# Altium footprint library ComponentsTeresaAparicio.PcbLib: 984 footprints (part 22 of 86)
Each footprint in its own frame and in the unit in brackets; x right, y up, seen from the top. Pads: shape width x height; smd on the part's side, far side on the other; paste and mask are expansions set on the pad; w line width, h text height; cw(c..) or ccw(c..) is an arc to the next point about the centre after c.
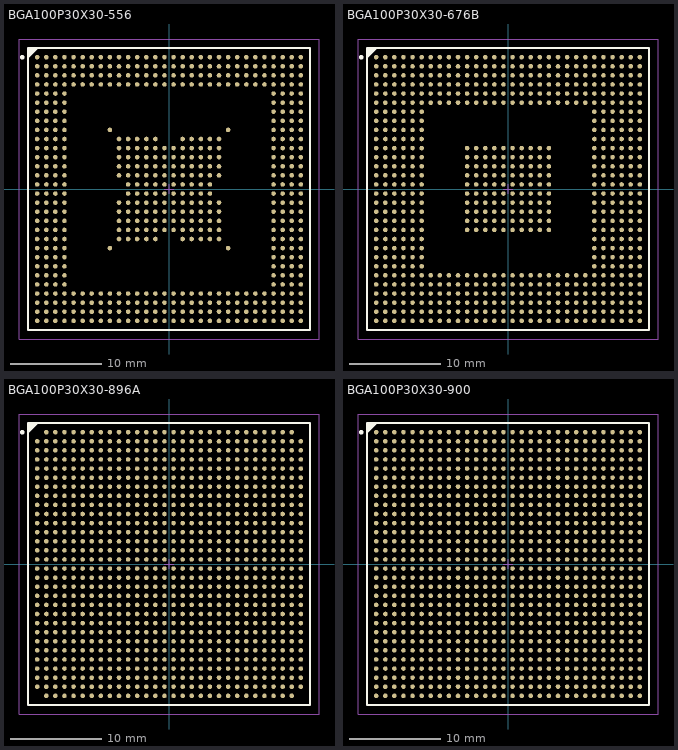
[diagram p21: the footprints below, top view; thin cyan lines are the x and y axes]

## BGA100P30X30-556 [mm] "556-Ball Fine Pitch Ball Grid Array 1.00 mm Pitch (FG556)"
height 2.6
pads (556):
  round 0.5 smd: A1(-14.5,14.5) A2(-13.5,14.5) A3(-12.5,14.5) A4(-11.5,14.5) A5(-10.5,14.5) A6(-9.5,14.5) A7(-8.5,14.5) A8(-7.5,14.5) A9(-6.5,14.5) A10(-5.5,14.5) A11(-4.5,14.5) A12(-3.5,14.5) A13(-2.5,14.5) A14(-1.5,14.5) A15(-0.5,14.5) A16(0.5,14.5) A17(1.5,14.5) A18(2.5,14.5) A19(3.5,14.5) A20(4.5,14.5) A21(5.5,14.5) A22(6.5,14.5) A23(7.5,14.5) A24(8.5,14.5) A25(9.5,14.5) A26(10.5,14.5) A27(11.5,14.5) A28(12.5,14.5) A29(13.5,14.5) A30(14.5,14.5) AA1(-14.5,-5.5) AA2(-13.5,-5.5) AA3(-12.5,-5.5) AA4(-11.5,-5.5) AA10(-5.5,-5.5) AA11(-4.5,-5.5) AA12(-3.5,-5.5) AA13(-2.5,-5.5) AA14(-1.5,-5.5) AA17(1.5,-5.5) AA18(2.5,-5.5) AA19(3.5,-5.5) AA20(4.5,-5.5) AA21(5.5,-5.5) AA27(11.5,-5.5) AA28(12.5,-5.5) AA29(13.5,-5.5) AA30(14.5,-5.5) AB1(-14.5,-6.5) AB2(-13.5,-6.5) AB3(-12.5,-6.5) AB4(-11.5,-6.5) AB9(-6.5,-6.5) AB22(6.5,-6.5) AB27(11.5,-6.5) AB28(12.5,-6.5) AB29(13.5,-6.5) AB30(14.5,-6.5) AC1(-14.5,-7.5) AC2(-13.5,-7.5) AC3(-12.5,-7.5) AC4(-11.5,-7.5) AC27(11.5,-7.5) AC28(12.5,-7.5) AC29(13.5,-7.5) AC30(14.5,-7.5) AD1(-14.5,-8.5) AD2(-13.5,-8.5) AD3(-12.5,-8.5) AD4(-11.5,-8.5) AD27(11.5,-8.5) AD28(12.5,-8.5) AD29(13.5,-8.5) AD30(14.5,-8.5) AE1(-14.5,-9.5) AE2(-13.5,-9.5) AE3(-12.5,-9.5) AE4(-11.5,-9.5) AE27(11.5,-9.5) AE28(12.5,-9.5) AE29(13.5,-9.5) AE30(14.5,-9.5) AF1(-14.5,-10.5) AF2(-13.5,-10.5) AF3(-12.5,-10.5) AF4(-11.5,-10.5) AF27(11.5,-10.5) AF28(12.5,-10.5) AF29(13.5,-10.5) AF30(14.5,-10.5) AG1(-14.5,-11.5) AG2(-13.5,-11.5) AG3(-12.5,-11.5) AG4(-11.5,-11.5) AG5(-10.5,-11.5) AG6(-9.5,-11.5) AG7(-8.5,-11.5) AG8(-7.5,-11.5) AG9(-6.5,-11.5) AG10(-5.5,-11.5) AG11(-4.5,-11.5) AG12(-3.5,-11.5) AG13(-2.5,-11.5) AG14(-1.5,-11.5) AG15(-0.5,-11.5) AG16(0.5,-11.5) AG17(1.5,-11.5) AG18(2.5,-11.5) AG19(3.5,-11.5) AG20(4.5,-11.5) AG21(5.5,-11.5) AG22(6.5,-11.5) AG23(7.5,-11.5) AG24(8.5,-11.5) AG25(9.5,-11.5) AG26(10.5,-11.5) AG27(11.5,-11.5) AG28(12.5,-11.5) AG29(13.5,-11.5) AG30(14.5,-11.5) AH1(-14.5,-12.5) AH2(-13.5,-12.5) AH3(-12.5,-12.5) AH4(-11.5,-12.5) AH5(-10.5,-12.5) AH6(-9.5,-12.5) AH7(-8.5,-12.5) AH8(-7.5,-12.5) AH9(-6.5,-12.5) AH10(-5.5,-12.5) AH11(-4.5,-12.5) AH12(-3.5,-12.5) AH13(-2.5,-12.5) AH14(-1.5,-12.5) AH15(-0.5,-12.5) AH16(0.5,-12.5) AH17(1.5,-12.5) AH18(2.5,-12.5) AH19(3.5,-12.5) AH20(4.5,-12.5) AH21(5.5,-12.5) AH22(6.5,-12.5) AH23(7.5,-12.5) AH24(8.5,-12.5) AH25(9.5,-12.5) AH26(10.5,-12.5) AH27(11.5,-12.5) AH28(12.5,-12.5) AH29(13.5,-12.5) AH30(14.5,-12.5) AJ1(-14.5,-13.5) AJ2(-13.5,-13.5) AJ3(-12.5,-13.5) AJ4(-11.5,-13.5) AJ5(-10.5,-13.5) AJ6(-9.5,-13.5) AJ7(-8.5,-13.5) AJ8(-7.5,-13.5) AJ9(-6.5,-13.5) AJ10(-5.5,-13.5) AJ11(-4.5,-13.5) AJ12(-3.5,-13.5) AJ13(-2.5,-13.5) AJ14(-1.5,-13.5) AJ15(-0.5,-13.5) AJ16(0.5,-13.5) AJ17(1.5,-13.5) AJ18(2.5,-13.5) AJ19(3.5,-13.5) AJ20(4.5,-13.5) AJ21(5.5,-13.5) AJ22(6.5,-13.5) AJ23(7.5,-13.5) AJ24(8.5,-13.5) AJ25(9.5,-13.5) AJ26(10.5,-13.5) AJ27(11.5,-13.5) AJ28(12.5,-13.5) AJ29(13.5,-13.5) AJ30(14.5,-13.5) AK1(-14.5,-14.5) AK2(-13.5,-14.5) AK3(-12.5,-14.5) AK4(-11.5,-14.5) AK5(-10.5,-14.5) AK6(-9.5,-14.5) AK7(-8.5,-14.5) AK8(-7.5,-14.5) AK9(-6.5,-14.5) AK10(-5.5,-14.5) AK11(-4.5,-14.5) AK12(-3.5,-14.5) AK13(-2.5,-14.5) AK14(-1.5,-14.5) AK15(-0.5,-14.5) AK16(0.5,-14.5) AK17(1.5,-14.5) AK18(2.5,-14.5) AK19(3.5,-14.5) AK20(4.5,-14.5) AK21(5.5,-14.5) AK22(6.5,-14.5) AK23(7.5,-14.5) AK24(8.5,-14.5) AK25(9.5,-14.5) AK26(10.5,-14.5) AK27(11.5,-14.5) AK28(12.5,-14.5) AK29(13.5,-14.5) AK30(14.5,-14.5) B1(-14.5,13.5) B2(-13.5,13.5) B3(-12.5,13.5) B4(-11.5,13.5) B5(-10.5,13.5) B6(-9.5,13.5) B7(-8.5,13.5) B8(-7.5,13.5) B9(-6.5,13.5) B10(-5.5,13.5) B11(-4.5,13.5) B12(-3.5,13.5) B13(-2.5,13.5) B14(-1.5,13.5) B15(-0.5,13.5) B16(0.5,13.5) B17(1.5,13.5) B18(2.5,13.5) B19(3.5,13.5) B20(4.5,13.5) B21(5.5,13.5) B22(6.5,13.5) B23(7.5,13.5) B24(8.5,13.5) B25(9.5,13.5) B26(10.5,13.5) B27(11.5,13.5) B28(12.5,13.5) B29(13.5,13.5) B30(14.5,13.5) C1(-14.5,12.5) C2(-13.5,12.5) C3(-12.5,12.5) C4(-11.5,12.5) C5(-10.5,12.5) C6(-9.5,12.5) C7(-8.5,12.5) C8(-7.5,12.5) C9(-6.5,12.5) C10(-5.5,12.5) C11(-4.5,12.5) C12(-3.5,12.5) C13(-2.5,12.5) C14(-1.5,12.5) C15(-0.5,12.5) C16(0.5,12.5) C17(1.5,12.5) C18(2.5,12.5) C19(3.5,12.5) C20(4.5,12.5) C21(5.5,12.5) C22(6.5,12.5) C23(7.5,12.5) C24(8.5,12.5) C25(9.5,12.5) C26(10.5,12.5) C27(11.5,12.5) C28(12.5,12.5) C29(13.5,12.5) C30(14.5,12.5) D1(-14.5,11.5) D2(-13.5,11.5) D3(-12.5,11.5) D4(-11.5,11.5) D5(-10.5,11.5) D6(-9.5,11.5) D7(-8.5,11.5) D8(-7.5,11.5) D9(-6.5,11.5) D10(-5.5,11.5) D11(-4.5,11.5) D12(-3.5,11.5) D13(-2.5,11.5) D14(-1.5,11.5) D15(-0.5,11.5) D16(0.5,11.5) D17(1.5,11.5) D18(2.5,11.5) D19(3.5,11.5) D20(4.5,11.5) D21(5.5,11.5) D22(6.5,11.5) D23(7.5,11.5) D24(8.5,11.5) D25(9.5,11.5) D26(10.5,11.5) D27(11.5,11.5) D28(12.5,11.5) D29(13.5,11.5) D30(14.5,11.5) E1(-14.5,10.5) E2(-13.5,10.5) E3(-12.5,10.5) E4(-11.5,10.5) E27(11.5,10.5) E28(12.5,10.5) E29(13.5,10.5) E30(14.5,10.5) F1(-14.5,9.5) F2(-13.5,9.5) F3(-12.5,9.5) F4(-11.5,9.5) F27(11.5,9.5) F28(12.5,9.5) F29(13.5,9.5) F30(14.5,9.5) G1(-14.5,8.5) G2(-13.5,8.5) G3(-12.5,8.5) G4(-11.5,8.5) G27(11.5,8.5) G28(12.5,8.5) G29(13.5,8.5) G30(14.5,8.5) H1(-14.5,7.5) H2(-13.5,7.5) H3(-12.5,7.5) H4(-11.5,7.5) H27(11.5,7.5) H28(12.5,7.5) H29(13.5,7.5) H30(14.5,7.5) J1(-14.5,6.5) J2(-13.5,6.5) J3(-12.5,6.5) J4(-11.5,6.5) J9(-6.5,6.5) J22(6.5,6.5) J27(11.5,6.5) J28(12.5,6.5) J29(13.5,6.5) J30(14.5,6.5) K1(-14.5,5.5) K2(-13.5,5.5) K3(-12.5,5.5) K4(-11.5,5.5) K10(-5.5,5.5) K11(-4.5,5.5) K12(-3.5,5.5) K13(-2.5,5.5) K14(-1.5,5.5) K17(1.5,5.5) K18(2.5,5.5) K19(3.5,5.5) K20(4.5,5.5) K21(5.5,5.5) K27(11.5,5.5) K28(12.5,5.5) K29(13.5,5.5) K30(14.5,5.5) L1(-14.5,4.5) L2(-13.5,4.5) L3(-12.5,4.5) L4(-11.5,4.5) L10(-5.5,4.5) L11(-4.5,4.5) L12(-3.5,4.5) L13(-2.5,4.5) L14(-1.5,4.5) L15(-0.5,4.5) L16(0.5,4.5) L17(1.5,4.5) L18(2.5,4.5) L19(3.5,4.5) L20(4.5,4.5) L21(5.5,4.5) L27(11.5,4.5) L28(12.5,4.5) L29(13.5,4.5) L30(14.5,4.5) M1(-14.5,3.5) M2(-13.5,3.5) M3(-12.5,3.5) M4(-11.5,3.5) M10(-5.5,3.5) M11(-4.5,3.5) M12(-3.5,3.5) M13(-2.5,3.5) M14(-1.5,3.5) M15(-0.5,3.5) M16(0.5,3.5) M17(1.5,3.5) M18(2.5,3.5) M19(3.5,3.5) M20(4.5,3.5) M21(5.5,3.5) M27(11.5,3.5) M28(12.5,3.5) M29(13.5,3.5) M30(14.5,3.5) N1(-14.5,2.5) N2(-13.5,2.5) N3(-12.5,2.5) N4(-11.5,2.5) N10(-5.5,2.5) N11(-4.5,2.5) N12(-3.5,2.5) N13(-2.5,2.5) N14(-1.5,2.5) N15(-0.5,2.5) N16(0.5,2.5) N17(1.5,2.5) N18(2.5,2.5) N19(3.5,2.5) N20(4.5,2.5) N21(5.5,2.5) N27(11.5,2.5) N28(12.5,2.5) N29(13.5,2.5) N30(14.5,2.5) P1(-14.5,1.5) P2(-13.5,1.5) P3(-12.5,1.5) P4(-11.5,1.5) P10(-5.5,1.5) P11(-4.5,1.5) P12(-3.5,1.5) P13(-2.5,1.5) P14(-1.5,1.5) P15(-0.5,1.5) P16(0.5,1.5) P17(1.5,1.5) P18(2.5,1.5) P19(3.5,1.5) P20(4.5,1.5) P21(5.5,1.5) P27(11.5,1.5) P28(12.5,1.5) P29(13.5,1.5) P30(14.5,1.5) R1(-14.5,0.5) R2(-13.5,0.5) R3(-12.5,0.5) R4(-11.5,0.5) R11(-4.5,0.5) R12(-3.5,0.5) R13(-2.5,0.5) R14(-1.5,0.5) R15(-0.5,0.5) R16(0.5,0.5) R17(1.5,0.5) R18(2.5,0.5) R19(3.5,0.5) R20(4.5,0.5) R27(11.5,0.5) R28(12.5,0.5) R29(13.5,0.5) R30(14.5,0.5) T1(-14.5,-0.5) T2(-13.5,-0.5) T3(-12.5,-0.5) T4(-11.5,-0.5) T11(-4.5,-0.5) T12(-3.5,-0.5) T13(-2.5,-0.5) T14(-1.5,-0.5) T15(-0.5,-0.5) T16(0.5,-0.5) T17(1.5,-0.5) T18(2.5,-0.5) T19(3.5,-0.5) T20(4.5,-0.5) T27(11.5,-0.5) T28(12.5,-0.5) T29(13.5,-0.5) T30(14.5,-0.5) U1(-14.5,-1.5) U2(-13.5,-1.5) U3(-12.5,-1.5) U4(-11.5,-1.5) U10(-5.5,-1.5) U11(-4.5,-1.5) U12(-3.5,-1.5) U13(-2.5,-1.5) U14(-1.5,-1.5) U15(-0.5,-1.5) U16(0.5,-1.5) U17(1.5,-1.5) U18(2.5,-1.5) U19(3.5,-1.5) U20(4.5,-1.5) U21(5.5,-1.5) U27(11.5,-1.5) U28(12.5,-1.5) U29(13.5,-1.5) U30(14.5,-1.5) V1(-14.5,-2.5) V2(-13.5,-2.5) V3(-12.5,-2.5) V4(-11.5,-2.5) V10(-5.5,-2.5) V11(-4.5,-2.5) V12(-3.5,-2.5) V13(-2.5,-2.5) V14(-1.5,-2.5) V15(-0.5,-2.5) V16(0.5,-2.5) V17(1.5,-2.5) V18(2.5,-2.5) V19(3.5,-2.5) V20(4.5,-2.5) V21(5.5,-2.5) V27(11.5,-2.5) V28(12.5,-2.5) V29(13.5,-2.5) V30(14.5,-2.5) W1(-14.5,-3.5) W2(-13.5,-3.5) W3(-12.5,-3.5) W4(-11.5,-3.5) W10(-5.5,-3.5) W11(-4.5,-3.5) W12(-3.5,-3.5) W13(-2.5,-3.5) W14(-1.5,-3.5) W15(-0.5,-3.5) W16(0.5,-3.5) W17(1.5,-3.5) W18(2.5,-3.5) W19(3.5,-3.5) W20(4.5,-3.5) W21(5.5,-3.5) W27(11.5,-3.5) W28(12.5,-3.5) W29(13.5,-3.5) W30(14.5,-3.5) Y1(-14.5,-4.5) Y2(-13.5,-4.5) Y3(-12.5,-4.5) Y4(-11.5,-4.5) Y10(-5.5,-4.5) Y11(-4.5,-4.5) Y12(-3.5,-4.5) Y13(-2.5,-4.5) Y14(-1.5,-4.5) Y15(-0.5,-4.5) Y16(0.5,-4.5) Y17(1.5,-4.5) Y18(2.5,-4.5) Y19(3.5,-4.5) Y20(4.5,-4.5) Y21(5.5,-4.5) Y27(11.5,-4.5) Y28(12.5,-4.5) Y29(13.5,-4.5) Y30(14.5,-4.5)
Top Overlay:
  circle w0.25: c-16.15,14.5 r0.125
  region: -14.5,15.5 -15.5,14.5 -15.5,15.5
  lines w0.2: -15.5,14.5 -14.5,15.5 ; -15.5,-15.5 -15.5,15.5 15.5,15.5 15.5,-15.5 -15.5,-15.5
Mechanical 13:
  lines w0.1: -15.5,-15.5 -15.5,15.5 15.5,15.5 15.5,-15.5 -15.5,-15.5
Mechanical 15:
  lines w0.1: -0.5,0 0.5,0 ; 0,-0.5 0,0.5 ; -16.5,-16.5 -16.5,16.5 16.5,16.5 16.5,-16.5 -16.5,-16.5
3D body: height 0, standoff 0, extent -15.5,-15.5 15.5,15.5

## BGA100P30X30-676B [mm] "BGA, 676-Leads, Body 31x31mm, Pitch 1mm"
height 2.6
pads (676):
  round 0.5 smd: A1(-14.5,14.5) A2(-13.5,14.5) A3(-12.5,14.5) A4(-11.5,14.5) A5(-10.5,14.5) A6(-9.5,14.5) A7(-8.5,14.5) A8(-7.5,14.5) A9(-6.5,14.5) A10(-5.5,14.5) A11(-4.5,14.5) A12(-3.5,14.5) A13(-2.5,14.5) A14(-1.5,14.5) A15(-0.5,14.5) A16(0.5,14.5) A17(1.5,14.5) A18(2.5,14.5) A19(3.5,14.5) A20(4.5,14.5) A21(5.5,14.5) A22(6.5,14.5) A23(7.5,14.5) A24(8.5,14.5) A25(9.5,14.5) A26(10.5,14.5) A27(11.5,14.5) A28(12.5,14.5) A29(13.5,14.5) A30(14.5,14.5) AA1(-14.5,-5.5) AA2(-13.5,-5.5) AA3(-12.5,-5.5) AA4(-11.5,-5.5) AA5(-10.5,-5.5) AA6(-9.5,-5.5) AA25(9.5,-5.5) AA26(10.5,-5.5) AA27(11.5,-5.5) AA28(12.5,-5.5) AA29(13.5,-5.5) AA30(14.5,-5.5) AB1(-14.5,-6.5) AB2(-13.5,-6.5) AB3(-12.5,-6.5) AB4(-11.5,-6.5) AB5(-10.5,-6.5) AB6(-9.5,-6.5) AB25(9.5,-6.5) AB26(10.5,-6.5) AB27(11.5,-6.5) AB28(12.5,-6.5) AB29(13.5,-6.5) AB30(14.5,-6.5) AC1(-14.5,-7.5) AC2(-13.5,-7.5) AC3(-12.5,-7.5) AC4(-11.5,-7.5) AC5(-10.5,-7.5) AC6(-9.5,-7.5) AC25(9.5,-7.5) AC26(10.5,-7.5) AC27(11.5,-7.5) AC28(12.5,-7.5) AC29(13.5,-7.5) AC30(14.5,-7.5) AD1(-14.5,-8.5) AD2(-13.5,-8.5) AD3(-12.5,-8.5) AD4(-11.5,-8.5) AD5(-10.5,-8.5) AD6(-9.5,-8.5) AD25(9.5,-8.5) AD26(10.5,-8.5) AD27(11.5,-8.5) AD28(12.5,-8.5) AD29(13.5,-8.5) AD30(14.5,-8.5) AE1(-14.5,-9.5) AE2(-13.5,-9.5) AE3(-12.5,-9.5) AE4(-11.5,-9.5) AE5(-10.5,-9.5) AE6(-9.5,-9.5) AE7(-8.5,-9.5) AE8(-7.5,-9.5) AE9(-6.5,-9.5) AE10(-5.5,-9.5) AE11(-4.5,-9.5) AE12(-3.5,-9.5) AE13(-2.5,-9.5) AE14(-1.5,-9.5) AE15(-0.5,-9.5) AE16(0.5,-9.5) AE17(1.5,-9.5) AE18(2.5,-9.5) AE19(3.5,-9.5) AE20(4.5,-9.5) AE21(5.5,-9.5) AE22(6.5,-9.5) AE23(7.5,-9.5) AE24(8.5,-9.5) AE25(9.5,-9.5) AE26(10.5,-9.5) AE27(11.5,-9.5) AE28(12.5,-9.5) AE29(13.5,-9.5) AE30(14.5,-9.5) AF1(-14.5,-10.5) AF2(-13.5,-10.5) AF3(-12.5,-10.5) AF4(-11.5,-10.5) AF5(-10.5,-10.5) AF6(-9.5,-10.5) AF7(-8.5,-10.5) AF8(-7.5,-10.5) AF9(-6.5,-10.5) AF10(-5.5,-10.5) AF11(-4.5,-10.5) AF12(-3.5,-10.5) AF13(-2.5,-10.5) AF14(-1.5,-10.5) AF15(-0.5,-10.5) AF16(0.5,-10.5) AF17(1.5,-10.5) AF18(2.5,-10.5) AF19(3.5,-10.5) AF20(4.5,-10.5) AF21(5.5,-10.5) AF22(6.5,-10.5) AF23(7.5,-10.5) AF24(8.5,-10.5) AF25(9.5,-10.5) AF26(10.5,-10.5) AF27(11.5,-10.5) AF28(12.5,-10.5) AF29(13.5,-10.5) AF30(14.5,-10.5) AG1(-14.5,-11.5) AG2(-13.5,-11.5) AG3(-12.5,-11.5) AG4(-11.5,-11.5) AG5(-10.5,-11.5) AG6(-9.5,-11.5) AG7(-8.5,-11.5) AG8(-7.5,-11.5) AG9(-6.5,-11.5) AG10(-5.5,-11.5) AG11(-4.5,-11.5) AG12(-3.5,-11.5) AG13(-2.5,-11.5) AG14(-1.5,-11.5) AG15(-0.5,-11.5) AG16(0.5,-11.5) AG17(1.5,-11.5) AG18(2.5,-11.5) AG19(3.5,-11.5) AG20(4.5,-11.5) AG21(5.5,-11.5) AG22(6.5,-11.5) AG23(7.5,-11.5) AG24(8.5,-11.5) AG25(9.5,-11.5) AG26(10.5,-11.5) AG27(11.5,-11.5) AG28(12.5,-11.5) AG29(13.5,-11.5) AG30(14.5,-11.5) AH1(-14.5,-12.5) AH2(-13.5,-12.5) AH3(-12.5,-12.5) AH4(-11.5,-12.5) AH5(-10.5,-12.5) AH6(-9.5,-12.5) AH7(-8.5,-12.5) AH8(-7.5,-12.5) AH9(-6.5,-12.5) AH10(-5.5,-12.5) AH11(-4.5,-12.5) AH12(-3.5,-12.5) AH13(-2.5,-12.5) AH14(-1.5,-12.5) AH15(-0.5,-12.5) AH16(0.5,-12.5) AH17(1.5,-12.5) AH18(2.5,-12.5) AH19(3.5,-12.5) AH20(4.5,-12.5) AH21(5.5,-12.5) AH22(6.5,-12.5) AH23(7.5,-12.5) AH24(8.5,-12.5) AH25(9.5,-12.5) AH26(10.5,-12.5) AH27(11.5,-12.5) AH28(12.5,-12.5) AH29(13.5,-12.5) AH30(14.5,-12.5) AJ1(-14.5,-13.5) AJ2(-13.5,-13.5) AJ3(-12.5,-13.5) AJ4(-11.5,-13.5) AJ5(-10.5,-13.5) AJ6(-9.5,-13.5) AJ7(-8.5,-13.5) AJ8(-7.5,-13.5) AJ9(-6.5,-13.5) AJ10(-5.5,-13.5) AJ11(-4.5,-13.5) AJ12(-3.5,-13.5) AJ13(-2.5,-13.5) AJ14(-1.5,-13.5) AJ15(-0.5,-13.5) AJ16(0.5,-13.5) AJ17(1.5,-13.5) AJ18(2.5,-13.5) AJ19(3.5,-13.5) AJ20(4.5,-13.5) AJ21(5.5,-13.5) AJ22(6.5,-13.5) AJ23(7.5,-13.5) AJ24(8.5,-13.5) AJ25(9.5,-13.5) AJ26(10.5,-13.5) AJ27(11.5,-13.5) AJ28(12.5,-13.5) AJ29(13.5,-13.5) AJ30(14.5,-13.5) AK1(-14.5,-14.5) AK2(-13.5,-14.5) AK3(-12.5,-14.5) AK4(-11.5,-14.5) AK5(-10.5,-14.5) AK6(-9.5,-14.5) AK7(-8.5,-14.5) AK8(-7.5,-14.5) AK9(-6.5,-14.5) AK10(-5.5,-14.5) AK11(-4.5,-14.5) AK12(-3.5,-14.5) AK13(-2.5,-14.5) AK14(-1.5,-14.5) AK15(-0.5,-14.5) AK16(0.5,-14.5) AK17(1.5,-14.5) AK18(2.5,-14.5) AK19(3.5,-14.5) AK20(4.5,-14.5) AK21(5.5,-14.5) AK22(6.5,-14.5) AK23(7.5,-14.5) AK24(8.5,-14.5) AK25(9.5,-14.5) AK26(10.5,-14.5) AK27(11.5,-14.5) AK28(12.5,-14.5) AK29(13.5,-14.5) AK30(14.5,-14.5) B1(-14.5,13.5) B2(-13.5,13.5) B3(-12.5,13.5) B4(-11.5,13.5) B5(-10.5,13.5) B6(-9.5,13.5) B7(-8.5,13.5) B8(-7.5,13.5) B9(-6.5,13.5) B10(-5.5,13.5) B11(-4.5,13.5) B12(-3.5,13.5) B13(-2.5,13.5) B14(-1.5,13.5) B15(-0.5,13.5) B16(0.5,13.5) B17(1.5,13.5) B18(2.5,13.5) B19(3.5,13.5) B20(4.5,13.5) B21(5.5,13.5) B22(6.5,13.5) B23(7.5,13.5) B24(8.5,13.5) B25(9.5,13.5) B26(10.5,13.5) B27(11.5,13.5) B28(12.5,13.5) B29(13.5,13.5) B30(14.5,13.5) C1(-14.5,12.5) C2(-13.5,12.5) C3(-12.5,12.5) C4(-11.5,12.5) C5(-10.5,12.5) C6(-9.5,12.5) C7(-8.5,12.5) C8(-7.5,12.5) C9(-6.5,12.5) C10(-5.5,12.5) C11(-4.5,12.5) C12(-3.5,12.5) C13(-2.5,12.5) C14(-1.5,12.5) C15(-0.5,12.5) C16(0.5,12.5) C17(1.5,12.5) C18(2.5,12.5) C19(3.5,12.5) C20(4.5,12.5) C21(5.5,12.5) C22(6.5,12.5) C23(7.5,12.5) C24(8.5,12.5) C25(9.5,12.5) C26(10.5,12.5) C27(11.5,12.5) C28(12.5,12.5) C29(13.5,12.5) C30(14.5,12.5) D1(-14.5,11.5) D2(-13.5,11.5) D3(-12.5,11.5) D4(-11.5,11.5) D5(-10.5,11.5) D6(-9.5,11.5) D7(-8.5,11.5) D8(-7.5,11.5) D9(-6.5,11.5) D10(-5.5,11.5) D11(-4.5,11.5) D12(-3.5,11.5) D13(-2.5,11.5) D14(-1.5,11.5) D15(-0.5,11.5) D16(0.5,11.5) D17(1.5,11.5) D18(2.5,11.5) D19(3.5,11.5) D20(4.5,11.5) D21(5.5,11.5) D22(6.5,11.5) D23(7.5,11.5) D24(8.5,11.5) D25(9.5,11.5) D26(10.5,11.5) D27(11.5,11.5) D28(12.5,11.5) D29(13.5,11.5) D30(14.5,11.5) E1(-14.5,10.5) E2(-13.5,10.5) E3(-12.5,10.5) E4(-11.5,10.5) E5(-10.5,10.5) E6(-9.5,10.5) E7(-8.5,10.5) E8(-7.5,10.5) E9(-6.5,10.5) E10(-5.5,10.5) E11(-4.5,10.5) E12(-3.5,10.5) E13(-2.5,10.5) E14(-1.5,10.5) E15(-0.5,10.5) E16(0.5,10.5) E17(1.5,10.5) E18(2.5,10.5) E19(3.5,10.5) E20(4.5,10.5) E21(5.5,10.5) E22(6.5,10.5) E23(7.5,10.5) E24(8.5,10.5) E25(9.5,10.5) E26(10.5,10.5) E27(11.5,10.5) E28(12.5,10.5) E29(13.5,10.5) E30(14.5,10.5) F1(-14.5,9.5) F2(-13.5,9.5) F3(-12.5,9.5) F4(-11.5,9.5) F5(-10.5,9.5) F6(-9.5,9.5) F7(-8.5,9.5) F8(-7.5,9.5) F9(-6.5,9.5) F10(-5.5,9.5) F11(-4.5,9.5) F12(-3.5,9.5) F13(-2.5,9.5) F14(-1.5,9.5) F15(-0.5,9.5) F16(0.5,9.5) F17(1.5,9.5) F18(2.5,9.5) F19(3.5,9.5) F20(4.5,9.5) F21(5.5,9.5) F22(6.5,9.5) F23(7.5,9.5) F24(8.5,9.5) F25(9.5,9.5) F26(10.5,9.5) F27(11.5,9.5) F28(12.5,9.5) F29(13.5,9.5) F30(14.5,9.5) G1(-14.5,8.5) G2(-13.5,8.5) G3(-12.5,8.5) G4(-11.5,8.5) G5(-10.5,8.5) G6(-9.5,8.5) G25(9.5,8.5) G26(10.5,8.5) G27(11.5,8.5) G28(12.5,8.5) G29(13.5,8.5) G30(14.5,8.5) H1(-14.5,7.5) H2(-13.5,7.5) H3(-12.5,7.5) H4(-11.5,7.5) H5(-10.5,7.5) H6(-9.5,7.5) H25(9.5,7.5) H26(10.5,7.5) H27(11.5,7.5) H28(12.5,7.5) H29(13.5,7.5) H30(14.5,7.5) J1(-14.5,6.5) J2(-13.5,6.5) J3(-12.5,6.5) J4(-11.5,6.5) J5(-10.5,6.5) J6(-9.5,6.5) J25(9.5,6.5) J26(10.5,6.5) J27(11.5,6.5) J28(12.5,6.5) J29(13.5,6.5) J30(14.5,6.5) K1(-14.5,5.5) K2(-13.5,5.5) K3(-12.5,5.5) K4(-11.5,5.5) K5(-10.5,5.5) K6(-9.5,5.5) K25(9.5,5.5) K26(10.5,5.5) K27(11.5,5.5) K28(12.5,5.5) K29(13.5,5.5) K30(14.5,5.5) L1(-14.5,4.5) L2(-13.5,4.5) L3(-12.5,4.5) L4(-11.5,4.5) L5(-10.5,4.5) L6(-9.5,4.5) L11(-4.5,4.5) L12(-3.5,4.5) L13(-2.5,4.5) L14(-1.5,4.5) L15(-0.5,4.5) L16(0.5,4.5) L17(1.5,4.5) L18(2.5,4.5) L19(3.5,4.5) L20(4.5,4.5) L25(9.5,4.5) L26(10.5,4.5) L27(11.5,4.5) L28(12.5,4.5) L29(13.5,4.5) L30(14.5,4.5) M1(-14.5,3.5) M2(-13.5,3.5) M3(-12.5,3.5) M4(-11.5,3.5) M5(-10.5,3.5) M6(-9.5,3.5) M11(-4.5,3.5) M12(-3.5,3.5) M13(-2.5,3.5) M14(-1.5,3.5) M15(-0.5,3.5) M16(0.5,3.5) M17(1.5,3.5) M18(2.5,3.5) M19(3.5,3.5) M20(4.5,3.5) M25(9.5,3.5) M26(10.5,3.5) M27(11.5,3.5) M28(12.5,3.5) M29(13.5,3.5) M30(14.5,3.5) N1(-14.5,2.5) N2(-13.5,2.5) N3(-12.5,2.5) N4(-11.5,2.5) N5(-10.5,2.5) N6(-9.5,2.5) N11(-4.5,2.5) N12(-3.5,2.5) N13(-2.5,2.5) N14(-1.5,2.5) N15(-0.5,2.5) N16(0.5,2.5) N17(1.5,2.5) N18(2.5,2.5) N19(3.5,2.5) N20(4.5,2.5) N25(9.5,2.5) N26(10.5,2.5) N27(11.5,2.5) N28(12.5,2.5) N29(13.5,2.5) N30(14.5,2.5) P1(-14.5,1.5) P2(-13.5,1.5) P3(-12.5,1.5) P4(-11.5,1.5) P5(-10.5,1.5) P6(-9.5,1.5) P11(-4.5,1.5) P12(-3.5,1.5) P13(-2.5,1.5) P14(-1.5,1.5) P15(-0.5,1.5) P16(0.5,1.5) P17(1.5,1.5) P18(2.5,1.5) P19(3.5,1.5) P20(4.5,1.5) P25(9.5,1.5) P26(10.5,1.5) P27(11.5,1.5) P28(12.5,1.5) P29(13.5,1.5) P30(14.5,1.5) R1(-14.5,0.5) R2(-13.5,0.5) R3(-12.5,0.5) R4(-11.5,0.5) R5(-10.5,0.5) R6(-9.5,0.5) R11(-4.5,0.5) R12(-3.5,0.5) R13(-2.5,0.5) R14(-1.5,0.5) R15(-0.5,0.5) R16(0.5,0.5) R17(1.5,0.5) R18(2.5,0.5) R19(3.5,0.5) R20(4.5,0.5) R25(9.5,0.5) R26(10.5,0.5) R27(11.5,0.5) R28(12.5,0.5) R29(13.5,0.5) R30(14.5,0.5) T1(-14.5,-0.5) T2(-13.5,-0.5) T3(-12.5,-0.5) T4(-11.5,-0.5) T5(-10.5,-0.5) T6(-9.5,-0.5) T11(-4.5,-0.5) T12(-3.5,-0.5) T13(-2.5,-0.5) T14(-1.5,-0.5) T15(-0.5,-0.5) T16(0.5,-0.5) T17(1.5,-0.5) T18(2.5,-0.5) T19(3.5,-0.5) T20(4.5,-0.5) T25(9.5,-0.5) T26(10.5,-0.5) T27(11.5,-0.5) T28(12.5,-0.5) T29(13.5,-0.5) T30(14.5,-0.5) U1(-14.5,-1.5) U2(-13.5,-1.5) U3(-12.5,-1.5) U4(-11.5,-1.5) U5(-10.5,-1.5) U6(-9.5,-1.5) U11(-4.5,-1.5) U12(-3.5,-1.5) U13(-2.5,-1.5) U14(-1.5,-1.5) U15(-0.5,-1.5) U16(0.5,-1.5) U17(1.5,-1.5) U18(2.5,-1.5) U19(3.5,-1.5) U20(4.5,-1.5) U25(9.5,-1.5) U26(10.5,-1.5) U27(11.5,-1.5) U28(12.5,-1.5) U29(13.5,-1.5) U30(14.5,-1.5) V1(-14.5,-2.5) V2(-13.5,-2.5) V3(-12.5,-2.5) V4(-11.5,-2.5) V5(-10.5,-2.5) V6(-9.5,-2.5) V11(-4.5,-2.5) V12(-3.5,-2.5) V13(-2.5,-2.5) V14(-1.5,-2.5) V15(-0.5,-2.5) V16(0.5,-2.5) V17(1.5,-2.5) V18(2.5,-2.5) V19(3.5,-2.5) V20(4.5,-2.5) V25(9.5,-2.5) V26(10.5,-2.5) V27(11.5,-2.5) V28(12.5,-2.5) V29(13.5,-2.5) V30(14.5,-2.5) W1(-14.5,-3.5) W2(-13.5,-3.5) W3(-12.5,-3.5) W4(-11.5,-3.5) W5(-10.5,-3.5) W6(-9.5,-3.5) W11(-4.5,-3.5) W12(-3.5,-3.5) W13(-2.5,-3.5) W14(-1.5,-3.5) W15(-0.5,-3.5) W16(0.5,-3.5) W17(1.5,-3.5) W18(2.5,-3.5) W19(3.5,-3.5) W20(4.5,-3.5) W25(9.5,-3.5) W26(10.5,-3.5) W27(11.5,-3.5) W28(12.5,-3.5) W29(13.5,-3.5) W30(14.5,-3.5) Y1(-14.5,-4.5) Y2(-13.5,-4.5) Y3(-12.5,-4.5) Y4(-11.5,-4.5) Y5(-10.5,-4.5) Y6(-9.5,-4.5) Y11(-4.5,-4.5) Y12(-3.5,-4.5) Y13(-2.5,-4.5) Y14(-1.5,-4.5) Y15(-0.5,-4.5) Y16(0.5,-4.5) Y17(1.5,-4.5) Y18(2.5,-4.5) Y19(3.5,-4.5) Y20(4.5,-4.5) Y25(9.5,-4.5) Y26(10.5,-4.5) Y27(11.5,-4.5) Y28(12.5,-4.5) Y29(13.5,-4.5) Y30(14.5,-4.5)
Top Overlay:
  circle w0.25: c-16.15,14.5 r0.125
  region: -14.5,15.5 -15.5,14.5 -15.5,15.5
  lines w0.2: -15.5,14.5 -14.5,15.5 ; -15.5,-15.5 15.5,-15.5 15.5,15.5 -15.5,15.5 -15.5,-15.5
Mechanical 13:
  lines w0.1: -15.5,-15.5 15.5,-15.5 15.5,15.5 -15.5,15.5 -15.5,-15.5
Mechanical 15:
  lines w0.1: -0.5,0 0.5,0 ; 0,-0.5 0,0.5 ; -16.5,-16.5 16.5,-16.5 16.5,16.5 -16.5,16.5 -16.5,-16.5
3D body: height 0, standoff 0, extent -15.5,-15.5 15.5,15.5

## BGA100P30X30-896A [mm] "BGA, 896-Leads, Body 31x31mm, Pitch 1mm"
height 2.44
pads (896):
  round 0.5 smd: A2(-13.5,14.5) A3(-12.5,14.5) A4(-11.5,14.5) A5(-10.5,14.5) A6(-9.5,14.5) A7(-8.5,14.5) A8(-7.5,14.5) A9(-6.5,14.5) A10(-5.5,14.5) A11(-4.5,14.5) A12(-3.5,14.5) A13(-2.5,14.5) A14(-1.5,14.5) A15(-0.5,14.5) A16(0.5,14.5) A17(1.5,14.5) A18(2.5,14.5) A19(3.5,14.5) A20(4.5,14.5) A21(5.5,14.5) A22(6.5,14.5) A23(7.5,14.5) A24(8.5,14.5) A25(9.5,14.5) A26(10.5,14.5) A27(11.5,14.5) A28(12.5,14.5) A29(13.5,14.5) AA1(-14.5,-5.5) AA2(-13.5,-5.5) AA3(-12.5,-5.5) AA4(-11.5,-5.5) AA5(-10.5,-5.5) AA6(-9.5,-5.5) AA7(-8.5,-5.5) AA8(-7.5,-5.5) AA9(-6.5,-5.5) AA10(-5.5,-5.5) AA11(-4.5,-5.5) AA12(-3.5,-5.5) AA13(-2.5,-5.5) AA14(-1.5,-5.5) AA15(-0.5,-5.5) AA16(0.5,-5.5) AA17(1.5,-5.5) AA18(2.5,-5.5) AA19(3.5,-5.5) AA20(4.5,-5.5) AA21(5.5,-5.5) AA22(6.5,-5.5) AA23(7.5,-5.5) AA24(8.5,-5.5) AA25(9.5,-5.5) AA26(10.5,-5.5) AA27(11.5,-5.5) AA28(12.5,-5.5) AA29(13.5,-5.5) AA30(14.5,-5.5) AB1(-14.5,-6.5) AB2(-13.5,-6.5) AB3(-12.5,-6.5) AB4(-11.5,-6.5) AB5(-10.5,-6.5) AB6(-9.5,-6.5) AB7(-8.5,-6.5) AB8(-7.5,-6.5) AB9(-6.5,-6.5) AB10(-5.5,-6.5) AB11(-4.5,-6.5) AB12(-3.5,-6.5) AB13(-2.5,-6.5) AB14(-1.5,-6.5) AB15(-0.5,-6.5) AB16(0.5,-6.5) AB17(1.5,-6.5) AB18(2.5,-6.5) AB19(3.5,-6.5) AB20(4.5,-6.5) AB21(5.5,-6.5) AB22(6.5,-6.5) AB23(7.5,-6.5) AB24(8.5,-6.5) AB25(9.5,-6.5) AB26(10.5,-6.5) AB27(11.5,-6.5) AB28(12.5,-6.5) AB29(13.5,-6.5) AB30(14.5,-6.5) AC1(-14.5,-7.5) AC2(-13.5,-7.5) AC3(-12.5,-7.5) AC4(-11.5,-7.5) AC5(-10.5,-7.5) AC6(-9.5,-7.5) AC7(-8.5,-7.5) AC8(-7.5,-7.5) AC9(-6.5,-7.5) AC10(-5.5,-7.5) AC11(-4.5,-7.5) AC12(-3.5,-7.5) AC13(-2.5,-7.5) AC14(-1.5,-7.5) AC15(-0.5,-7.5) AC16(0.5,-7.5) AC17(1.5,-7.5) AC18(2.5,-7.5) AC19(3.5,-7.5) AC20(4.5,-7.5) AC21(5.5,-7.5) AC22(6.5,-7.5) AC23(7.5,-7.5) AC24(8.5,-7.5) AC25(9.5,-7.5) AC26(10.5,-7.5) AC27(11.5,-7.5) AC28(12.5,-7.5) AC29(13.5,-7.5) AC30(14.5,-7.5) AD1(-14.5,-8.5) AD2(-13.5,-8.5) AD3(-12.5,-8.5) AD4(-11.5,-8.5) AD5(-10.5,-8.5) AD6(-9.5,-8.5) AD7(-8.5,-8.5) AD8(-7.5,-8.5) AD9(-6.5,-8.5) AD10(-5.5,-8.5) AD11(-4.5,-8.5) AD12(-3.5,-8.5) AD13(-2.5,-8.5) AD14(-1.5,-8.5) AD15(-0.5,-8.5) AD16(0.5,-8.5) AD17(1.5,-8.5) AD18(2.5,-8.5) AD19(3.5,-8.5) AD20(4.5,-8.5) AD21(5.5,-8.5) AD22(6.5,-8.5) AD23(7.5,-8.5) AD24(8.5,-8.5) AD25(9.5,-8.5) AD26(10.5,-8.5) AD27(11.5,-8.5) AD28(12.5,-8.5) AD29(13.5,-8.5) AD30(14.5,-8.5) AE1(-14.5,-9.5) AE2(-13.5,-9.5) AE3(-12.5,-9.5) AE4(-11.5,-9.5) AE5(-10.5,-9.5) AE6(-9.5,-9.5) AE7(-8.5,-9.5) AE8(-7.5,-9.5) AE9(-6.5,-9.5) AE10(-5.5,-9.5) AE11(-4.5,-9.5) AE12(-3.5,-9.5) AE13(-2.5,-9.5) AE14(-1.5,-9.5) AE15(-0.5,-9.5) AE16(0.5,-9.5) AE17(1.5,-9.5) AE18(2.5,-9.5) AE19(3.5,-9.5) AE20(4.5,-9.5) AE21(5.5,-9.5) AE22(6.5,-9.5) AE23(7.5,-9.5) AE24(8.5,-9.5) AE25(9.5,-9.5) AE26(10.5,-9.5) AE27(11.5,-9.5) AE28(12.5,-9.5) AE29(13.5,-9.5) AE30(14.5,-9.5) AF1(-14.5,-10.5) AF2(-13.5,-10.5) AF3(-12.5,-10.5) AF4(-11.5,-10.5) AF5(-10.5,-10.5) AF6(-9.5,-10.5) AF7(-8.5,-10.5) AF8(-7.5,-10.5) AF9(-6.5,-10.5) AF10(-5.5,-10.5) AF11(-4.5,-10.5) AF12(-3.5,-10.5) AF13(-2.5,-10.5) AF14(-1.5,-10.5) AF15(-0.5,-10.5) AF16(0.5,-10.5) AF17(1.5,-10.5) AF18(2.5,-10.5) AF19(3.5,-10.5) AF20(4.5,-10.5) AF21(5.5,-10.5) AF22(6.5,-10.5) AF23(7.5,-10.5) AF24(8.5,-10.5) AF25(9.5,-10.5) AF26(10.5,-10.5) AF27(11.5,-10.5) AF28(12.5,-10.5) AF29(13.5,-10.5) AF30(14.5,-10.5) AG1(-14.5,-11.5) AG2(-13.5,-11.5) AG3(-12.5,-11.5) AG4(-11.5,-11.5) AG5(-10.5,-11.5) AG6(-9.5,-11.5) AG7(-8.5,-11.5) AG8(-7.5,-11.5) AG9(-6.5,-11.5) AG10(-5.5,-11.5) AG11(-4.5,-11.5) AG12(-3.5,-11.5) AG13(-2.5,-11.5) AG14(-1.5,-11.5) AG15(-0.5,-11.5) AG16(0.5,-11.5) AG17(1.5,-11.5) AG18(2.5,-11.5) AG19(3.5,-11.5) AG20(4.5,-11.5) AG21(5.5,-11.5) AG22(6.5,-11.5) AG23(7.5,-11.5) AG24(8.5,-11.5) AG25(9.5,-11.5) AG26(10.5,-11.5) AG27(11.5,-11.5) AG28(12.5,-11.5) AG29(13.5,-11.5) AG30(14.5,-11.5) AH1(-14.5,-12.5) AH2(-13.5,-12.5) AH3(-12.5,-12.5) AH4(-11.5,-12.5) AH5(-10.5,-12.5) AH6(-9.5,-12.5) AH7(-8.5,-12.5) AH8(-7.5,-12.5) AH9(-6.5,-12.5) AH10(-5.5,-12.5) AH11(-4.5,-12.5) AH12(-3.5,-12.5) AH13(-2.5,-12.5) AH14(-1.5,-12.5) AH15(-0.5,-12.5) AH16(0.5,-12.5) AH17(1.5,-12.5) AH18(2.5,-12.5) AH19(3.5,-12.5) AH20(4.5,-12.5) AH21(5.5,-12.5) AH22(6.5,-12.5) AH23(7.5,-12.5) AH24(8.5,-12.5) AH25(9.5,-12.5) AH26(10.5,-12.5) AH27(11.5,-12.5) AH28(12.5,-12.5) AH29(13.5,-12.5) AH30(14.5,-12.5) AJ1(-14.5,-13.5) AJ2(-13.5,-13.5) AJ3(-12.5,-13.5) AJ4(-11.5,-13.5) AJ5(-10.5,-13.5) AJ6(-9.5,-13.5) AJ7(-8.5,-13.5) AJ8(-7.5,-13.5) AJ9(-6.5,-13.5) AJ10(-5.5,-13.5) AJ11(-4.5,-13.5) AJ12(-3.5,-13.5) AJ13(-2.5,-13.5) AJ14(-1.5,-13.5) AJ15(-0.5,-13.5) AJ16(0.5,-13.5) AJ17(1.5,-13.5) AJ18(2.5,-13.5) AJ19(3.5,-13.5) AJ20(4.5,-13.5) AJ21(5.5,-13.5) AJ22(6.5,-13.5) AJ23(7.5,-13.5) AJ24(8.5,-13.5) AJ25(9.5,-13.5) AJ26(10.5,-13.5) AJ27(11.5,-13.5) AJ28(12.5,-13.5) AJ29(13.5,-13.5) AJ30(14.5,-13.5) AK2(-13.5,-14.5) AK3(-12.5,-14.5) AK4(-11.5,-14.5) AK5(-10.5,-14.5) AK6(-9.5,-14.5) AK7(-8.5,-14.5) AK8(-7.5,-14.5) AK9(-6.5,-14.5) AK10(-5.5,-14.5) AK11(-4.5,-14.5) AK12(-3.5,-14.5) AK13(-2.5,-14.5) AK14(-1.5,-14.5) AK15(-0.5,-14.5) AK16(0.5,-14.5) AK17(1.5,-14.5) AK18(2.5,-14.5) AK19(3.5,-14.5) AK20(4.5,-14.5) AK21(5.5,-14.5) AK22(6.5,-14.5) AK23(7.5,-14.5) AK24(8.5,-14.5) AK25(9.5,-14.5) AK26(10.5,-14.5) AK27(11.5,-14.5) AK28(12.5,-14.5) AK29(13.5,-14.5) B1(-14.5,13.5) B2(-13.5,13.5) B3(-12.5,13.5) B4(-11.5,13.5) B5(-10.5,13.5) B6(-9.5,13.5) B7(-8.5,13.5) B8(-7.5,13.5) B9(-6.5,13.5) B10(-5.5,13.5) B11(-4.5,13.5) B12(-3.5,13.5) B13(-2.5,13.5) B14(-1.5,13.5) B15(-0.5,13.5) B16(0.5,13.5) B17(1.5,13.5) B18(2.5,13.5) B19(3.5,13.5) B20(4.5,13.5) B21(5.5,13.5) B22(6.5,13.5) B23(7.5,13.5) B24(8.5,13.5) B25(9.5,13.5) B26(10.5,13.5) B27(11.5,13.5) B28(12.5,13.5) B29(13.5,13.5) B30(14.5,13.5) C1(-14.5,12.5) C2(-13.5,12.5) C3(-12.5,12.5) C4(-11.5,12.5) C5(-10.5,12.5) C6(-9.5,12.5) C7(-8.5,12.5) C8(-7.5,12.5) C9(-6.5,12.5) C10(-5.5,12.5) C11(-4.5,12.5) C12(-3.5,12.5) C13(-2.5,12.5) C14(-1.5,12.5) C15(-0.5,12.5) C16(0.5,12.5) C17(1.5,12.5) C18(2.5,12.5) C19(3.5,12.5) C20(4.5,12.5) C21(5.5,12.5) C22(6.5,12.5) C23(7.5,12.5) C24(8.5,12.5) C25(9.5,12.5) C26(10.5,12.5) C27(11.5,12.5) C28(12.5,12.5) C29(13.5,12.5) C30(14.5,12.5) D1(-14.5,11.5) D2(-13.5,11.5) D3(-12.5,11.5) D4(-11.5,11.5) D5(-10.5,11.5) D6(-9.5,11.5) D7(-8.5,11.5) D8(-7.5,11.5) D9(-6.5,11.5) D10(-5.5,11.5) D11(-4.5,11.5) D12(-3.5,11.5) D13(-2.5,11.5) D14(-1.5,11.5) D15(-0.5,11.5) D16(0.5,11.5) D17(1.5,11.5) D18(2.5,11.5) D19(3.5,11.5) D20(4.5,11.5) D21(5.5,11.5) D22(6.5,11.5) D23(7.5,11.5) D24(8.5,11.5) D25(9.5,11.5) D26(10.5,11.5) D27(11.5,11.5) D28(12.5,11.5) D29(13.5,11.5) D30(14.5,11.5) E1(-14.5,10.5) E2(-13.5,10.5) E3(-12.5,10.5) E4(-11.5,10.5) E5(-10.5,10.5) E6(-9.5,10.5) E7(-8.5,10.5) E8(-7.5,10.5) E9(-6.5,10.5) E10(-5.5,10.5) E11(-4.5,10.5) E12(-3.5,10.5) E13(-2.5,10.5) E14(-1.5,10.5) E15(-0.5,10.5) E16(0.5,10.5) E17(1.5,10.5) E18(2.5,10.5) E19(3.5,10.5) E20(4.5,10.5) E21(5.5,10.5) E22(6.5,10.5) E23(7.5,10.5) E24(8.5,10.5) E25(9.5,10.5) E26(10.5,10.5) E27(11.5,10.5) E28(12.5,10.5) E29(13.5,10.5) E30(14.5,10.5) F1(-14.5,9.5) F2(-13.5,9.5) F3(-12.5,9.5) F4(-11.5,9.5) F5(-10.5,9.5) F6(-9.5,9.5) F7(-8.5,9.5) F8(-7.5,9.5) F9(-6.5,9.5) F10(-5.5,9.5) F11(-4.5,9.5) F12(-3.5,9.5) F13(-2.5,9.5) F14(-1.5,9.5) F15(-0.5,9.5) F16(0.5,9.5) F17(1.5,9.5) F18(2.5,9.5) F19(3.5,9.5) F20(4.5,9.5) F21(5.5,9.5) F22(6.5,9.5) F23(7.5,9.5) F24(8.5,9.5) F25(9.5,9.5) F26(10.5,9.5) F27(11.5,9.5) F28(12.5,9.5) F29(13.5,9.5) F30(14.5,9.5) G1(-14.5,8.5) G2(-13.5,8.5) G3(-12.5,8.5) G4(-11.5,8.5) G5(-10.5,8.5) G6(-9.5,8.5) G7(-8.5,8.5) G8(-7.5,8.5) G9(-6.5,8.5) G10(-5.5,8.5) G11(-4.5,8.5) G12(-3.5,8.5) G13(-2.5,8.5) G14(-1.5,8.5) G15(-0.5,8.5) G16(0.5,8.5) G17(1.5,8.5) G18(2.5,8.5) G19(3.5,8.5) G20(4.5,8.5) G21(5.5,8.5) G22(6.5,8.5) G23(7.5,8.5) G24(8.5,8.5) G25(9.5,8.5) G26(10.5,8.5) G27(11.5,8.5) G28(12.5,8.5) G29(13.5,8.5) G30(14.5,8.5) H1(-14.5,7.5) H2(-13.5,7.5) H3(-12.5,7.5) H4(-11.5,7.5) H5(-10.5,7.5) H6(-9.5,7.5) H7(-8.5,7.5) H8(-7.5,7.5) H9(-6.5,7.5) H10(-5.5,7.5) H11(-4.5,7.5) H12(-3.5,7.5) H13(-2.5,7.5) H14(-1.5,7.5) H15(-0.5,7.5) H16(0.5,7.5) H17(1.5,7.5) H18(2.5,7.5) H19(3.5,7.5) H20(4.5,7.5) H21(5.5,7.5) H22(6.5,7.5) H23(7.5,7.5) H24(8.5,7.5) H25(9.5,7.5) H26(10.5,7.5) H27(11.5,7.5) H28(12.5,7.5) H29(13.5,7.5) H30(14.5,7.5) J1(-14.5,6.5) J2(-13.5,6.5) J3(-12.5,6.5) J4(-11.5,6.5) J5(-10.5,6.5) J6(-9.5,6.5) J7(-8.5,6.5) J8(-7.5,6.5) J9(-6.5,6.5) J10(-5.5,6.5) J11(-4.5,6.5) J12(-3.5,6.5) J13(-2.5,6.5) J14(-1.5,6.5) J15(-0.5,6.5) J16(0.5,6.5) J17(1.5,6.5) J18(2.5,6.5) J19(3.5,6.5) J20(4.5,6.5) J21(5.5,6.5) J22(6.5,6.5) J23(7.5,6.5) J24(8.5,6.5) J25(9.5,6.5) J26(10.5,6.5) J27(11.5,6.5) J28(12.5,6.5) J29(13.5,6.5) J30(14.5,6.5) K1(-14.5,5.5) K2(-13.5,5.5) K3(-12.5,5.5) K4(-11.5,5.5) K5(-10.5,5.5) K6(-9.5,5.5) K7(-8.5,5.5) K8(-7.5,5.5) K9(-6.5,5.5) K10(-5.5,5.5) K11(-4.5,5.5) K12(-3.5,5.5) K13(-2.5,5.5) K14(-1.5,5.5) K15(-0.5,5.5) K16(0.5,5.5) K17(1.5,5.5) K18(2.5,5.5) K19(3.5,5.5) K20(4.5,5.5) K21(5.5,5.5) K22(6.5,5.5) K23(7.5,5.5) K24(8.5,5.5) K25(9.5,5.5) K26(10.5,5.5) K27(11.5,5.5) K28(12.5,5.5) K29(13.5,5.5) K30(14.5,5.5) L1(-14.5,4.5) L2(-13.5,4.5) L3(-12.5,4.5) L4(-11.5,4.5) L5(-10.5,4.5) L6(-9.5,4.5) L7(-8.5,4.5) L8(-7.5,4.5) L9(-6.5,4.5) L10(-5.5,4.5) L11(-4.5,4.5) L12(-3.5,4.5) L13(-2.5,4.5) L14(-1.5,4.5) L15(-0.5,4.5) L16(0.5,4.5) L17(1.5,4.5) L18(2.5,4.5) L19(3.5,4.5) L20(4.5,4.5) L21(5.5,4.5) L22(6.5,4.5) L23(7.5,4.5) L24(8.5,4.5) L25(9.5,4.5) L26(10.5,4.5) L27(11.5,4.5) L28(12.5,4.5) L29(13.5,4.5) L30(14.5,4.5) M1(-14.5,3.5) M2(-13.5,3.5) M3(-12.5,3.5) M4(-11.5,3.5) M5(-10.5,3.5) M6(-9.5,3.5) M7(-8.5,3.5) M8(-7.5,3.5) M9(-6.5,3.5) M10(-5.5,3.5) M11(-4.5,3.5) M12(-3.5,3.5) M13(-2.5,3.5) M14(-1.5,3.5) M15(-0.5,3.5) M16(0.5,3.5) M17(1.5,3.5) M18(2.5,3.5) M19(3.5,3.5) M20(4.5,3.5) M21(5.5,3.5) M22(6.5,3.5) M23(7.5,3.5) M24(8.5,3.5) M25(9.5,3.5) M26(10.5,3.5) M27(11.5,3.5) M28(12.5,3.5) M29(13.5,3.5) M30(14.5,3.5) N1(-14.5,2.5) N2(-13.5,2.5) N3(-12.5,2.5) N4(-11.5,2.5) N5(-10.5,2.5) N6(-9.5,2.5) N7(-8.5,2.5) N8(-7.5,2.5) N9(-6.5,2.5) N10(-5.5,2.5) N11(-4.5,2.5) N12(-3.5,2.5) N13(-2.5,2.5) N14(-1.5,2.5) N15(-0.5,2.5) N16(0.5,2.5) N17(1.5,2.5) N18(2.5,2.5) N19(3.5,2.5) N20(4.5,2.5) N21(5.5,2.5) N22(6.5,2.5) N23(7.5,2.5) N24(8.5,2.5) N25(9.5,2.5) N26(10.5,2.5) N27(11.5,2.5) N28(12.5,2.5) N29(13.5,2.5) N30(14.5,2.5) P1(-14.5,1.5) P2(-13.5,1.5) P3(-12.5,1.5) P4(-11.5,1.5) P5(-10.5,1.5) P6(-9.5,1.5) P7(-8.5,1.5) P8(-7.5,1.5) P9(-6.5,1.5) P10(-5.5,1.5) P11(-4.5,1.5) P12(-3.5,1.5) P13(-2.5,1.5) P14(-1.5,1.5) P15(-0.5,1.5) P16(0.5,1.5) P17(1.5,1.5) P18(2.5,1.5) P19(3.5,1.5) P20(4.5,1.5) P21(5.5,1.5) P22(6.5,1.5) P23(7.5,1.5) P24(8.5,1.5) P25(9.5,1.5) P26(10.5,1.5) P27(11.5,1.5) P28(12.5,1.5) P29(13.5,1.5) P30(14.5,1.5) R1(-14.5,0.5) R2(-13.5,0.5) R3(-12.5,0.5) R4(-11.5,0.5) R5(-10.5,0.5) R6(-9.5,0.5) R7(-8.5,0.5) R8(-7.5,0.5) R9(-6.5,0.5) R10(-5.5,0.5) R11(-4.5,0.5) R12(-3.5,0.5) R13(-2.5,0.5) R14(-1.5,0.5) R15(-0.5,0.5) R16(0.5,0.5) R17(1.5,0.5) R18(2.5,0.5) R19(3.5,0.5) R20(4.5,0.5) R21(5.5,0.5) R22(6.5,0.5) R23(7.5,0.5) R24(8.5,0.5) R25(9.5,0.5) R26(10.5,0.5) R27(11.5,0.5) R28(12.5,0.5) R29(13.5,0.5) R30(14.5,0.5) T1(-14.5,-0.5) T2(-13.5,-0.5) T3(-12.5,-0.5) T4(-11.5,-0.5) T5(-10.5,-0.5) T6(-9.5,-0.5) T7(-8.5,-0.5) T8(-7.5,-0.5) T9(-6.5,-0.5) T10(-5.5,-0.5) T11(-4.5,-0.5) T12(-3.5,-0.5) T13(-2.5,-0.5) T14(-1.5,-0.5) T15(-0.5,-0.5) T16(0.5,-0.5) T17(1.5,-0.5) T18(2.5,-0.5) T19(3.5,-0.5) T20(4.5,-0.5) T21(5.5,-0.5) T22(6.5,-0.5) T23(7.5,-0.5) T24(8.5,-0.5) T25(9.5,-0.5) T26(10.5,-0.5) T27(11.5,-0.5) T28(12.5,-0.5) T29(13.5,-0.5) T30(14.5,-0.5) U1(-14.5,-1.5) U2(-13.5,-1.5) U3(-12.5,-1.5) U4(-11.5,-1.5) U5(-10.5,-1.5) U6(-9.5,-1.5) U7(-8.5,-1.5) U8(-7.5,-1.5) U9(-6.5,-1.5) U10(-5.5,-1.5) U11(-4.5,-1.5) U12(-3.5,-1.5) U13(-2.5,-1.5) U14(-1.5,-1.5) U15(-0.5,-1.5) U16(0.5,-1.5) U17(1.5,-1.5) U18(2.5,-1.5) U19(3.5,-1.5) U20(4.5,-1.5) U21(5.5,-1.5) U22(6.5,-1.5) U23(7.5,-1.5) U24(8.5,-1.5) U25(9.5,-1.5) U26(10.5,-1.5) U27(11.5,-1.5) U28(12.5,-1.5) U29(13.5,-1.5) U30(14.5,-1.5) V1(-14.5,-2.5) V2(-13.5,-2.5) V3(-12.5,-2.5) V4(-11.5,-2.5) V5(-10.5,-2.5) V6(-9.5,-2.5) V7(-8.5,-2.5) V8(-7.5,-2.5) V9(-6.5,-2.5) V10(-5.5,-2.5) V11(-4.5,-2.5) V12(-3.5,-2.5) V13(-2.5,-2.5) V14(-1.5,-2.5) V15(-0.5,-2.5) V16(0.5,-2.5) V17(1.5,-2.5) V18(2.5,-2.5) V19(3.5,-2.5) V20(4.5,-2.5) V21(5.5,-2.5) V22(6.5,-2.5) V23(7.5,-2.5) V24(8.5,-2.5) V25(9.5,-2.5) V26(10.5,-2.5) V27(11.5,-2.5) V28(12.5,-2.5) V29(13.5,-2.5) V30(14.5,-2.5) W1(-14.5,-3.5) W2(-13.5,-3.5) W3(-12.5,-3.5) W4(-11.5,-3.5) W5(-10.5,-3.5) W6(-9.5,-3.5) W7(-8.5,-3.5) W8(-7.5,-3.5) W9(-6.5,-3.5) W10(-5.5,-3.5) W11(-4.5,-3.5) W12(-3.5,-3.5) W13(-2.5,-3.5) W14(-1.5,-3.5) W15(-0.5,-3.5) W16(0.5,-3.5) W17(1.5,-3.5) W18(2.5,-3.5) W19(3.5,-3.5) W20(4.5,-3.5) W21(5.5,-3.5) W22(6.5,-3.5) W23(7.5,-3.5) W24(8.5,-3.5) W25(9.5,-3.5) W26(10.5,-3.5) W27(11.5,-3.5) W28(12.5,-3.5) W29(13.5,-3.5) W30(14.5,-3.5) Y1(-14.5,-4.5) Y2(-13.5,-4.5) Y3(-12.5,-4.5) Y4(-11.5,-4.5) Y5(-10.5,-4.5) Y6(-9.5,-4.5) Y7(-8.5,-4.5) Y8(-7.5,-4.5) Y9(-6.5,-4.5) Y10(-5.5,-4.5) Y11(-4.5,-4.5) Y12(-3.5,-4.5) Y13(-2.5,-4.5) Y14(-1.5,-4.5) Y15(-0.5,-4.5) Y16(0.5,-4.5) Y17(1.5,-4.5) Y18(2.5,-4.5) Y19(3.5,-4.5) Y20(4.5,-4.5) Y21(5.5,-4.5) Y22(6.5,-4.5) Y23(7.5,-4.5) Y24(8.5,-4.5) Y25(9.5,-4.5) Y26(10.5,-4.5) Y27(11.5,-4.5) Y28(12.5,-4.5) Y29(13.5,-4.5) Y30(14.5,-4.5)
Top Overlay:
  circle w0.25: c-16.15,14.5 r0.125
  region: -14.5,15.5 -15.5,14.5 -15.5,15.5
  lines w0.2: -15.5,14.5 -14.5,15.5 ; -15.5,-15.5 -15.5,15.5 15.5,15.5 15.5,-15.5 -15.5,-15.5
Mechanical 13:
  lines w0.1: -15.5,-15.5 -15.5,15.5 15.5,15.5 15.5,-15.5 -15.5,-15.5
Mechanical 15:
  lines w0.1: -0.5,0 0.5,0 ; 0,-0.5 0,0.5 ; -16.5,-16.5 -16.5,16.5 16.5,16.5 16.5,-16.5 -16.5,-16.5
3D body: height 0, standoff 0, extent -15.5,-15.5 15.5,15.5

## BGA100P30X30-900 [mm] "BGA, 900-Leads, Body 31x31mm, Pitch 1mm"
height 3.5
pads (900):
  round 0.5 smd: A1(-14.5,14.5) A2(-13.5,14.5) A3(-12.5,14.5) A4(-11.5,14.5) A5(-10.5,14.5) A6(-9.5,14.5) A7(-8.5,14.5) A8(-7.5,14.5) A9(-6.5,14.5) A10(-5.5,14.5) A11(-4.5,14.5) A12(-3.5,14.5) A13(-2.5,14.5) A14(-1.5,14.5) A15(-0.5,14.5) A16(0.5,14.5) A17(1.5,14.5) A18(2.5,14.5) A19(3.5,14.5) A20(4.5,14.5) A21(5.5,14.5) A22(6.5,14.5) A23(7.5,14.5) A24(8.5,14.5) A25(9.5,14.5) A26(10.5,14.5) A27(11.5,14.5) A28(12.5,14.5) A29(13.5,14.5) A30(14.5,14.5) AA1(-14.5,-5.5) AA2(-13.5,-5.5) AA3(-12.5,-5.5) AA4(-11.5,-5.5) AA5(-10.5,-5.5) AA6(-9.5,-5.5) AA7(-8.5,-5.5) AA8(-7.5,-5.5) AA9(-6.5,-5.5) AA10(-5.5,-5.5) AA11(-4.5,-5.5) AA12(-3.5,-5.5) AA13(-2.5,-5.5) AA14(-1.5,-5.5) AA15(-0.5,-5.5) AA16(0.5,-5.5) AA17(1.5,-5.5) AA18(2.5,-5.5) AA19(3.5,-5.5) AA20(4.5,-5.5) AA21(5.5,-5.5) AA22(6.5,-5.5) AA23(7.5,-5.5) AA24(8.5,-5.5) AA25(9.5,-5.5) AA26(10.5,-5.5) AA27(11.5,-5.5) AA28(12.5,-5.5) AA29(13.5,-5.5) AA30(14.5,-5.5) AB1(-14.5,-6.5) AB2(-13.5,-6.5) AB3(-12.5,-6.5) AB4(-11.5,-6.5) AB5(-10.5,-6.5) AB6(-9.5,-6.5) AB7(-8.5,-6.5) AB8(-7.5,-6.5) AB9(-6.5,-6.5) AB10(-5.5,-6.5) AB11(-4.5,-6.5) AB12(-3.5,-6.5) AB13(-2.5,-6.5) AB14(-1.5,-6.5) AB15(-0.5,-6.5) AB16(0.5,-6.5) AB17(1.5,-6.5) AB18(2.5,-6.5) AB19(3.5,-6.5) AB20(4.5,-6.5) AB21(5.5,-6.5) AB22(6.5,-6.5) AB23(7.5,-6.5) AB24(8.5,-6.5) AB25(9.5,-6.5) AB26(10.5,-6.5) AB27(11.5,-6.5) AB28(12.5,-6.5) AB29(13.5,-6.5) AB30(14.5,-6.5) AC1(-14.5,-7.5) AC2(-13.5,-7.5) AC3(-12.5,-7.5) AC4(-11.5,-7.5) AC5(-10.5,-7.5) AC6(-9.5,-7.5) AC7(-8.5,-7.5) AC8(-7.5,-7.5) AC9(-6.5,-7.5) AC10(-5.5,-7.5) AC11(-4.5,-7.5) AC12(-3.5,-7.5) AC13(-2.5,-7.5) AC14(-1.5,-7.5) AC15(-0.5,-7.5) AC16(0.5,-7.5) AC17(1.5,-7.5) AC18(2.5,-7.5) AC19(3.5,-7.5) AC20(4.5,-7.5) AC21(5.5,-7.5) AC22(6.5,-7.5) AC23(7.5,-7.5) AC24(8.5,-7.5) AC25(9.5,-7.5) AC26(10.5,-7.5) AC27(11.5,-7.5) AC28(12.5,-7.5) AC29(13.5,-7.5) AC30(14.5,-7.5) AD1(-14.5,-8.5) AD2(-13.5,-8.5) AD3(-12.5,-8.5) AD4(-11.5,-8.5) AD5(-10.5,-8.5) AD6(-9.5,-8.5) AD7(-8.5,-8.5) AD8(-7.5,-8.5) AD9(-6.5,-8.5) AD10(-5.5,-8.5) AD11(-4.5,-8.5) AD12(-3.5,-8.5) AD13(-2.5,-8.5) AD14(-1.5,-8.5) AD15(-0.5,-8.5) AD16(0.5,-8.5) AD17(1.5,-8.5) AD18(2.5,-8.5) AD19(3.5,-8.5) AD20(4.5,-8.5) AD21(5.5,-8.5) AD22(6.5,-8.5) AD23(7.5,-8.5) AD24(8.5,-8.5) AD25(9.5,-8.5) AD26(10.5,-8.5) AD27(11.5,-8.5) AD28(12.5,-8.5) AD29(13.5,-8.5) AD30(14.5,-8.5) AE1(-14.5,-9.5) AE2(-13.5,-9.5) AE3(-12.5,-9.5) AE4(-11.5,-9.5) AE5(-10.5,-9.5) AE6(-9.5,-9.5) AE7(-8.5,-9.5) AE8(-7.5,-9.5) AE9(-6.5,-9.5) AE10(-5.5,-9.5) AE11(-4.5,-9.5) AE12(-3.5,-9.5) AE13(-2.5,-9.5) AE14(-1.5,-9.5) AE15(-0.5,-9.5) AE16(0.5,-9.5) AE17(1.5,-9.5) AE18(2.5,-9.5) AE19(3.5,-9.5) AE20(4.5,-9.5) AE21(5.5,-9.5) AE22(6.5,-9.5) AE23(7.5,-9.5) AE24(8.5,-9.5) AE25(9.5,-9.5) AE26(10.5,-9.5) AE27(11.5,-9.5) AE28(12.5,-9.5) AE29(13.5,-9.5) AE30(14.5,-9.5) AF1(-14.5,-10.5) AF2(-13.5,-10.5) AF3(-12.5,-10.5) AF4(-11.5,-10.5) AF5(-10.5,-10.5) AF6(-9.5,-10.5) AF7(-8.5,-10.5) AF8(-7.5,-10.5) AF9(-6.5,-10.5) AF10(-5.5,-10.5) AF11(-4.5,-10.5) AF12(-3.5,-10.5) AF13(-2.5,-10.5) AF14(-1.5,-10.5) AF15(-0.5,-10.5) AF16(0.5,-10.5) AF17(1.5,-10.5) AF18(2.5,-10.5) AF19(3.5,-10.5) AF20(4.5,-10.5) AF21(5.5,-10.5) AF22(6.5,-10.5) AF23(7.5,-10.5) AF24(8.5,-10.5) AF25(9.5,-10.5) AF26(10.5,-10.5) AF27(11.5,-10.5) AF28(12.5,-10.5) AF29(13.5,-10.5) AF30(14.5,-10.5) AG1(-14.5,-11.5) AG2(-13.5,-11.5) AG3(-12.5,-11.5) AG4(-11.5,-11.5) AG5(-10.5,-11.5) AG6(-9.5,-11.5) AG7(-8.5,-11.5) AG8(-7.5,-11.5) AG9(-6.5,-11.5) AG10(-5.5,-11.5) AG11(-4.5,-11.5) AG12(-3.5,-11.5) AG13(-2.5,-11.5) AG14(-1.5,-11.5) AG15(-0.5,-11.5) AG16(0.5,-11.5) AG17(1.5,-11.5) AG18(2.5,-11.5) AG19(3.5,-11.5) AG20(4.5,-11.5) AG21(5.5,-11.5) AG22(6.5,-11.5) AG23(7.5,-11.5) AG24(8.5,-11.5) AG25(9.5,-11.5) AG26(10.5,-11.5) AG27(11.5,-11.5) AG28(12.5,-11.5) AG29(13.5,-11.5) AG30(14.5,-11.5) AH1(-14.5,-12.5) AH2(-13.5,-12.5) AH3(-12.5,-12.5) AH4(-11.5,-12.5) AH5(-10.5,-12.5) AH6(-9.5,-12.5) AH7(-8.5,-12.5) AH8(-7.5,-12.5) AH9(-6.5,-12.5) AH10(-5.5,-12.5) AH11(-4.5,-12.5) AH12(-3.5,-12.5) AH13(-2.5,-12.5) AH14(-1.5,-12.5) AH15(-0.5,-12.5) AH16(0.5,-12.5) AH17(1.5,-12.5) AH18(2.5,-12.5) AH19(3.5,-12.5) AH20(4.5,-12.5) AH21(5.5,-12.5) AH22(6.5,-12.5) AH23(7.5,-12.5) AH24(8.5,-12.5) AH25(9.5,-12.5) AH26(10.5,-12.5) AH27(11.5,-12.5) AH28(12.5,-12.5) AH29(13.5,-12.5) AH30(14.5,-12.5) AJ1(-14.5,-13.5) AJ2(-13.5,-13.5) AJ3(-12.5,-13.5) AJ4(-11.5,-13.5) AJ5(-10.5,-13.5) AJ6(-9.5,-13.5) AJ7(-8.5,-13.5) AJ8(-7.5,-13.5) AJ9(-6.5,-13.5) AJ10(-5.5,-13.5) AJ11(-4.5,-13.5) AJ12(-3.5,-13.5) AJ13(-2.5,-13.5) AJ14(-1.5,-13.5) AJ15(-0.5,-13.5) AJ16(0.5,-13.5) AJ17(1.5,-13.5) AJ18(2.5,-13.5) AJ19(3.5,-13.5) AJ20(4.5,-13.5) AJ21(5.5,-13.5) AJ22(6.5,-13.5) AJ23(7.5,-13.5) AJ24(8.5,-13.5) AJ25(9.5,-13.5) AJ26(10.5,-13.5) AJ27(11.5,-13.5) AJ28(12.5,-13.5) AJ29(13.5,-13.5) AJ30(14.5,-13.5) AK1(-14.5,-14.5) AK2(-13.5,-14.5) AK3(-12.5,-14.5) AK4(-11.5,-14.5) AK5(-10.5,-14.5) AK6(-9.5,-14.5) AK7(-8.5,-14.5) AK8(-7.5,-14.5) AK9(-6.5,-14.5) AK10(-5.5,-14.5) AK11(-4.5,-14.5) AK12(-3.5,-14.5) AK13(-2.5,-14.5) AK14(-1.5,-14.5) AK15(-0.5,-14.5) AK16(0.5,-14.5) AK17(1.5,-14.5) AK18(2.5,-14.5) AK19(3.5,-14.5) AK20(4.5,-14.5) AK21(5.5,-14.5) AK22(6.5,-14.5) AK23(7.5,-14.5) AK24(8.5,-14.5) AK25(9.5,-14.5) AK26(10.5,-14.5) AK27(11.5,-14.5) AK28(12.5,-14.5) AK29(13.5,-14.5) AK30(14.5,-14.5) B1(-14.5,13.5) B2(-13.5,13.5) B3(-12.5,13.5) B4(-11.5,13.5) B5(-10.5,13.5) B6(-9.5,13.5) B7(-8.5,13.5) B8(-7.5,13.5) B9(-6.5,13.5) B10(-5.5,13.5) B11(-4.5,13.5) B12(-3.5,13.5) B13(-2.5,13.5) B14(-1.5,13.5) B15(-0.5,13.5) B16(0.5,13.5) B17(1.5,13.5) B18(2.5,13.5) B19(3.5,13.5) B20(4.5,13.5) B21(5.5,13.5) B22(6.5,13.5) B23(7.5,13.5) B24(8.5,13.5) B25(9.5,13.5) B26(10.5,13.5) B27(11.5,13.5) B28(12.5,13.5) B29(13.5,13.5) B30(14.5,13.5) C1(-14.5,12.5) C2(-13.5,12.5) C3(-12.5,12.5) C4(-11.5,12.5) C5(-10.5,12.5) C6(-9.5,12.5) C7(-8.5,12.5) C8(-7.5,12.5) C9(-6.5,12.5) C10(-5.5,12.5) C11(-4.5,12.5) C12(-3.5,12.5) C13(-2.5,12.5) C14(-1.5,12.5) C15(-0.5,12.5) C16(0.5,12.5) C17(1.5,12.5) C18(2.5,12.5) C19(3.5,12.5) C20(4.5,12.5) C21(5.5,12.5) C22(6.5,12.5) C23(7.5,12.5) C24(8.5,12.5) C25(9.5,12.5) C26(10.5,12.5) C27(11.5,12.5) C28(12.5,12.5) C29(13.5,12.5) C30(14.5,12.5) D1(-14.5,11.5) D2(-13.5,11.5) D3(-12.5,11.5) D4(-11.5,11.5) D5(-10.5,11.5) D6(-9.5,11.5) D7(-8.5,11.5) D8(-7.5,11.5) D9(-6.5,11.5) D10(-5.5,11.5) D11(-4.5,11.5) D12(-3.5,11.5) D13(-2.5,11.5) D14(-1.5,11.5) D15(-0.5,11.5) D16(0.5,11.5) D17(1.5,11.5) D18(2.5,11.5) D19(3.5,11.5) D20(4.5,11.5) D21(5.5,11.5) D22(6.5,11.5) D23(7.5,11.5) D24(8.5,11.5) D25(9.5,11.5) D26(10.5,11.5) D27(11.5,11.5) D28(12.5,11.5) D29(13.5,11.5) D30(14.5,11.5) E1(-14.5,10.5) E2(-13.5,10.5) E3(-12.5,10.5) E4(-11.5,10.5) E5(-10.5,10.5) E6(-9.5,10.5) E7(-8.5,10.5) E8(-7.5,10.5) E9(-6.5,10.5) E10(-5.5,10.5) E11(-4.5,10.5) E12(-3.5,10.5) E13(-2.5,10.5) E14(-1.5,10.5) E15(-0.5,10.5) E16(0.5,10.5) E17(1.5,10.5) E18(2.5,10.5) E19(3.5,10.5) E20(4.5,10.5) E21(5.5,10.5) E22(6.5,10.5) E23(7.5,10.5) E24(8.5,10.5) E25(9.5,10.5) E26(10.5,10.5) E27(11.5,10.5) E28(12.5,10.5) E29(13.5,10.5) E30(14.5,10.5) F1(-14.5,9.5) F2(-13.5,9.5) F3(-12.5,9.5) F4(-11.5,9.5) F5(-10.5,9.5) F6(-9.5,9.5) F7(-8.5,9.5) F8(-7.5,9.5) F9(-6.5,9.5) F10(-5.5,9.5) F11(-4.5,9.5) F12(-3.5,9.5) F13(-2.5,9.5) F14(-1.5,9.5) F15(-0.5,9.5) F16(0.5,9.5) F17(1.5,9.5) F18(2.5,9.5) F19(3.5,9.5) F20(4.5,9.5) F21(5.5,9.5) F22(6.5,9.5) F23(7.5,9.5) F24(8.5,9.5) F25(9.5,9.5) F26(10.5,9.5) F27(11.5,9.5) F28(12.5,9.5) F29(13.5,9.5) F30(14.5,9.5) G1(-14.5,8.5) G2(-13.5,8.5) G3(-12.5,8.5) G4(-11.5,8.5) G5(-10.5,8.5) G6(-9.5,8.5) G7(-8.5,8.5) G8(-7.5,8.5) G9(-6.5,8.5) G10(-5.5,8.5) G11(-4.5,8.5) G12(-3.5,8.5) G13(-2.5,8.5) G14(-1.5,8.5) G15(-0.5,8.5) G16(0.5,8.5) G17(1.5,8.5) G18(2.5,8.5) G19(3.5,8.5) G20(4.5,8.5) G21(5.5,8.5) G22(6.5,8.5) G23(7.5,8.5) G24(8.5,8.5) G25(9.5,8.5) G26(10.5,8.5) G27(11.5,8.5) G28(12.5,8.5) G29(13.5,8.5) G30(14.5,8.5) H1(-14.5,7.5) H2(-13.5,7.5) H3(-12.5,7.5) H4(-11.5,7.5) H5(-10.5,7.5) H6(-9.5,7.5) H7(-8.5,7.5) H8(-7.5,7.5) H9(-6.5,7.5) H10(-5.5,7.5) H11(-4.5,7.5) H12(-3.5,7.5) H13(-2.5,7.5) H14(-1.5,7.5) H15(-0.5,7.5) H16(0.5,7.5) H17(1.5,7.5) H18(2.5,7.5) H19(3.5,7.5) H20(4.5,7.5) H21(5.5,7.5) H22(6.5,7.5) H23(7.5,7.5) H24(8.5,7.5) H25(9.5,7.5) H26(10.5,7.5) H27(11.5,7.5) H28(12.5,7.5) H29(13.5,7.5) H30(14.5,7.5) J1(-14.5,6.5) J2(-13.5,6.5) J3(-12.5,6.5) J4(-11.5,6.5) J5(-10.5,6.5) J6(-9.5,6.5) J7(-8.5,6.5) J8(-7.5,6.5) J9(-6.5,6.5) J10(-5.5,6.5) J11(-4.5,6.5) J12(-3.5,6.5) J13(-2.5,6.5) J14(-1.5,6.5) J15(-0.5,6.5) J16(0.5,6.5) J17(1.5,6.5) J18(2.5,6.5) J19(3.5,6.5) J20(4.5,6.5) J21(5.5,6.5) J22(6.5,6.5) J23(7.5,6.5) J24(8.5,6.5) J25(9.5,6.5) J26(10.5,6.5) J27(11.5,6.5) J28(12.5,6.5) J29(13.5,6.5) J30(14.5,6.5) K1(-14.5,5.5) K2(-13.5,5.5) K3(-12.5,5.5) K4(-11.5,5.5) K5(-10.5,5.5) K6(-9.5,5.5) K7(-8.5,5.5) K8(-7.5,5.5) K9(-6.5,5.5) K10(-5.5,5.5) K11(-4.5,5.5) K12(-3.5,5.5) K13(-2.5,5.5) K14(-1.5,5.5) K15(-0.5,5.5) K16(0.5,5.5) K17(1.5,5.5) K18(2.5,5.5) K19(3.5,5.5) K20(4.5,5.5) K21(5.5,5.5) K22(6.5,5.5) K23(7.5,5.5) K24(8.5,5.5) K25(9.5,5.5) K26(10.5,5.5) K27(11.5,5.5) K28(12.5,5.5) K29(13.5,5.5) K30(14.5,5.5) L1(-14.5,4.5) L2(-13.5,4.5) L3(-12.5,4.5) L4(-11.5,4.5) L5(-10.5,4.5) L6(-9.5,4.5) L7(-8.5,4.5) L8(-7.5,4.5) L9(-6.5,4.5) L10(-5.5,4.5) L11(-4.5,4.5) L12(-3.5,4.5) L13(-2.5,4.5) L14(-1.5,4.5) L15(-0.5,4.5) L16(0.5,4.5) L17(1.5,4.5) L18(2.5,4.5) L19(3.5,4.5) L20(4.5,4.5) L21(5.5,4.5) L22(6.5,4.5) L23(7.5,4.5) L24(8.5,4.5) L25(9.5,4.5) L26(10.5,4.5) L27(11.5,4.5) L28(12.5,4.5) L29(13.5,4.5) L30(14.5,4.5) M1(-14.5,3.5) M2(-13.5,3.5) M3(-12.5,3.5) M4(-11.5,3.5) M5(-10.5,3.5) M6(-9.5,3.5) M7(-8.5,3.5) M8(-7.5,3.5) M9(-6.5,3.5) M10(-5.5,3.5) M11(-4.5,3.5) M12(-3.5,3.5) M13(-2.5,3.5) M14(-1.5,3.5) M15(-0.5,3.5) M16(0.5,3.5) M17(1.5,3.5) M18(2.5,3.5) M19(3.5,3.5) M20(4.5,3.5) M21(5.5,3.5) M22(6.5,3.5) M23(7.5,3.5) M24(8.5,3.5) M25(9.5,3.5) M26(10.5,3.5) M27(11.5,3.5) M28(12.5,3.5) M29(13.5,3.5) M30(14.5,3.5) N1(-14.5,2.5) N2(-13.5,2.5) N3(-12.5,2.5) N4(-11.5,2.5) N5(-10.5,2.5) N6(-9.5,2.5) N7(-8.5,2.5) N8(-7.5,2.5) N9(-6.5,2.5) N10(-5.5,2.5) N11(-4.5,2.5) N12(-3.5,2.5) N13(-2.5,2.5) N14(-1.5,2.5) N15(-0.5,2.5) N16(0.5,2.5) N17(1.5,2.5) N18(2.5,2.5) N19(3.5,2.5) N20(4.5,2.5) N21(5.5,2.5) N22(6.5,2.5) N23(7.5,2.5) N24(8.5,2.5) N25(9.5,2.5) N26(10.5,2.5) N27(11.5,2.5) N28(12.5,2.5) N29(13.5,2.5) N30(14.5,2.5) P1(-14.5,1.5) P2(-13.5,1.5) P3(-12.5,1.5) P4(-11.5,1.5) P5(-10.5,1.5) P6(-9.5,1.5) P7(-8.5,1.5) P8(-7.5,1.5) P9(-6.5,1.5) P10(-5.5,1.5) P11(-4.5,1.5) P12(-3.5,1.5) P13(-2.5,1.5) P14(-1.5,1.5) P15(-0.5,1.5) P16(0.5,1.5) P17(1.5,1.5) P18(2.5,1.5) P19(3.5,1.5) P20(4.5,1.5) P21(5.5,1.5) P22(6.5,1.5) P23(7.5,1.5) P24(8.5,1.5) P25(9.5,1.5) P26(10.5,1.5) P27(11.5,1.5) P28(12.5,1.5) P29(13.5,1.5) P30(14.5,1.5) R1(-14.5,0.5) R2(-13.5,0.5) R3(-12.5,0.5) R4(-11.5,0.5) R5(-10.5,0.5) R6(-9.5,0.5) R7(-8.5,0.5) R8(-7.5,0.5) R9(-6.5,0.5) R10(-5.5,0.5) R11(-4.5,0.5) R12(-3.5,0.5) R13(-2.5,0.5) R14(-1.5,0.5) R15(-0.5,0.5) R16(0.5,0.5) R17(1.5,0.5) R18(2.5,0.5) R19(3.5,0.5) R20(4.5,0.5) R21(5.5,0.5) R22(6.5,0.5) R23(7.5,0.5) R24(8.5,0.5) R25(9.5,0.5) R26(10.5,0.5) R27(11.5,0.5) R28(12.5,0.5) R29(13.5,0.5) R30(14.5,0.5) T1(-14.5,-0.5) T2(-13.5,-0.5) T3(-12.5,-0.5) T4(-11.5,-0.5) T5(-10.5,-0.5) T6(-9.5,-0.5) T7(-8.5,-0.5) T8(-7.5,-0.5) T9(-6.5,-0.5) T10(-5.5,-0.5) T11(-4.5,-0.5) T12(-3.5,-0.5) T13(-2.5,-0.5) T14(-1.5,-0.5) T15(-0.5,-0.5) T16(0.5,-0.5) T17(1.5,-0.5) T18(2.5,-0.5) T19(3.5,-0.5) T20(4.5,-0.5) T21(5.5,-0.5) T22(6.5,-0.5) T23(7.5,-0.5) T24(8.5,-0.5) T25(9.5,-0.5) T26(10.5,-0.5) T27(11.5,-0.5) T28(12.5,-0.5) T29(13.5,-0.5) T30(14.5,-0.5) U1(-14.5,-1.5) U2(-13.5,-1.5) U3(-12.5,-1.5) U4(-11.5,-1.5) U5(-10.5,-1.5) U6(-9.5,-1.5) U7(-8.5,-1.5) U8(-7.5,-1.5) U9(-6.5,-1.5) U10(-5.5,-1.5) U11(-4.5,-1.5) U12(-3.5,-1.5) U13(-2.5,-1.5) U14(-1.5,-1.5) U15(-0.5,-1.5) U16(0.5,-1.5) U17(1.5,-1.5) U18(2.5,-1.5) U19(3.5,-1.5) U20(4.5,-1.5) U21(5.5,-1.5) U22(6.5,-1.5) U23(7.5,-1.5) U24(8.5,-1.5) U25(9.5,-1.5) U26(10.5,-1.5) U27(11.5,-1.5) U28(12.5,-1.5) U29(13.5,-1.5) U30(14.5,-1.5) V1(-14.5,-2.5) V2(-13.5,-2.5) V3(-12.5,-2.5) V4(-11.5,-2.5) V5(-10.5,-2.5) V6(-9.5,-2.5) V7(-8.5,-2.5) V8(-7.5,-2.5) V9(-6.5,-2.5) V10(-5.5,-2.5) V11(-4.5,-2.5) V12(-3.5,-2.5) V13(-2.5,-2.5) V14(-1.5,-2.5) V15(-0.5,-2.5) V16(0.5,-2.5) V17(1.5,-2.5) V18(2.5,-2.5) V19(3.5,-2.5) V20(4.5,-2.5) V21(5.5,-2.5) V22(6.5,-2.5) V23(7.5,-2.5) V24(8.5,-2.5) V25(9.5,-2.5) V26(10.5,-2.5) V27(11.5,-2.5) V28(12.5,-2.5) V29(13.5,-2.5) V30(14.5,-2.5) W1(-14.5,-3.5) W2(-13.5,-3.5) W3(-12.5,-3.5) W4(-11.5,-3.5) W5(-10.5,-3.5) W6(-9.5,-3.5) W7(-8.5,-3.5) W8(-7.5,-3.5) W9(-6.5,-3.5) W10(-5.5,-3.5) W11(-4.5,-3.5) W12(-3.5,-3.5) W13(-2.5,-3.5) W14(-1.5,-3.5) W15(-0.5,-3.5) W16(0.5,-3.5) W17(1.5,-3.5) W18(2.5,-3.5) W19(3.5,-3.5) W20(4.5,-3.5) W21(5.5,-3.5) W22(6.5,-3.5) W23(7.5,-3.5) W24(8.5,-3.5) W25(9.5,-3.5) W26(10.5,-3.5) W27(11.5,-3.5) W28(12.5,-3.5) W29(13.5,-3.5) W30(14.5,-3.5) Y1(-14.5,-4.5) Y2(-13.5,-4.5) Y3(-12.5,-4.5) Y4(-11.5,-4.5) Y5(-10.5,-4.5) Y6(-9.5,-4.5) Y7(-8.5,-4.5) Y8(-7.5,-4.5) Y9(-6.5,-4.5) Y10(-5.5,-4.5) Y11(-4.5,-4.5) Y12(-3.5,-4.5) Y13(-2.5,-4.5) Y14(-1.5,-4.5) Y15(-0.5,-4.5) Y16(0.5,-4.5) Y17(1.5,-4.5) Y18(2.5,-4.5) Y19(3.5,-4.5) Y20(4.5,-4.5) Y21(5.5,-4.5) Y22(6.5,-4.5) Y23(7.5,-4.5) Y24(8.5,-4.5) Y25(9.5,-4.5) Y26(10.5,-4.5) Y27(11.5,-4.5) Y28(12.5,-4.5) Y29(13.5,-4.5) Y30(14.5,-4.5)
Top Overlay:
  circle w0.25: c-16.15,14.5 r0.125
  region: -14.5,15.5 -15.5,14.5 -15.5,15.5
  lines w0.2: -15.5,14.5 -14.5,15.5 ; -15.5,-15.5 -15.5,15.5 15.5,15.5 15.5,-15.5 -15.5,-15.5
Mechanical 13:
  lines w0.1: -15.5,-15.5 -15.5,15.5 15.5,15.5 15.5,-15.5 -15.5,-15.5
Mechanical 15:
  lines w0.1: -0.5,0 0.5,0 ; 0,-0.5 0,0.5 ; -16.5,-16.5 -16.5,16.5 16.5,16.5 16.5,-16.5 -16.5,-16.5
3D body: height 0, standoff 0, extent -15.5,-15.5 15.5,15.5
